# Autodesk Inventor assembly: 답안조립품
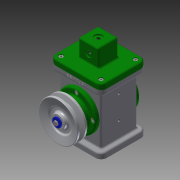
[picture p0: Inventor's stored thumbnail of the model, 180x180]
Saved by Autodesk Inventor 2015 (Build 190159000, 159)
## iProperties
Created: 2017-08
Part Number: 답안조립품
Document SubType Name: Assembly
Designer: Administrator
Author: Administrator
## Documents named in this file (18)
- C:\Users\Administrator\Desktop\470807V1002\답안조립품.iam
- C:\Users\Administrator\Desktop\470807V1002\답안본체.ipt
- C:\Users\Administrator\Desktop\470807V1002\E-링.ipt
- C:\Users\Administrator\Desktop\470807V1002\V-벨트풀리.ipt
- C:\Users\Administrator\Desktop\470807V1002\덮개.ipt
- C:\Users\Administrator\Desktop\470807V1002\뒤커버.ipt
- C:\Users\Administrator\Desktop\470807V1002\링크.ipt
- C:\Users\Administrator\Desktop\470807V1002\베어링 17 x 40 x 12.ipt
- C:\Users\Administrator\Desktop\470807V1002\볼트 M4 x 8.ipt
- C:\Users\Administrator\Desktop\470807V1002\볼트 M4 x 10.ipt
- C:\Users\Administrator\Desktop\470807V1002\슬라이더.ipt
- C:\Users\Administrator\Desktop\470807V1002\앞커버.ipt
- C:\Users\Administrator\Desktop\470807V1002\오일 실 17 30 8.ipt
- C:\Users\Administrator\Desktop\470807V1002\와셔 4x16.ipt
- C:\Users\Administrator\Desktop\470807V1002\클레비스 핀 6 x 22.ipt
- 클레비스 핀 6 x 22.ipt
- C:\Users\Administrator\Desktop\470807V1002\키 4 x 4 x 12.ipt
- C:\Users\Administrator\Desktop\470807V1002\편심축.ipt
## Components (2 placed, 2 different names)
1. E-링:1
2. V-벨트풀리:1
